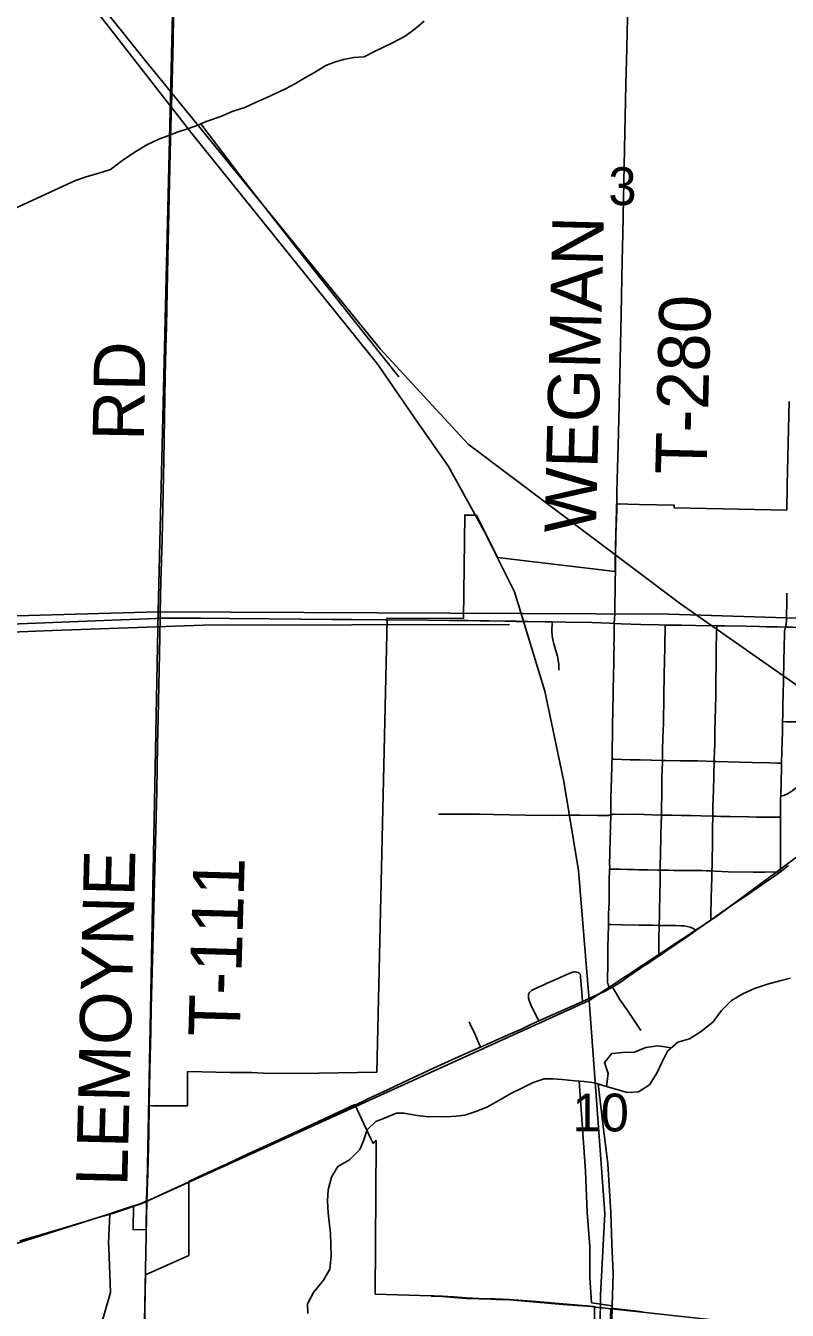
# Model space of a CAD drawing. Extents: x 0 to 34, y 0 to 22.
# Drawn here: x 3.939 to 4.781, y 16.776 to 18.197 of the extents above; entities that cross this region are included whole.
import ezdxf

# ---------------------------------------------------------------- set-up
doc = ezdxf.new("R2010")
doc.units = 0
for name, color, linetype in [('GM_X_City_Street', 7, 'Continuous'), ('GM_X_Corporation', 7, 'Continuous'), ('GM_X_Major_River', 7, 'Continuous'), ('GM_X_Minor_River', 7, 'Continuous'), ('GM_X_Rail_Line', 7, 'Continuous'), ('GM_X_Section', 7, 'Continuous'), ('GM_X_Section_Text', 7, 'Continuous'), ('GM_X_State_Route', 7, 'Continuous'), ('GM_X_Township_Road', 7, 'Continuous'), ('GM_X_Township_Road_Text', 7, 'Continuous')]:
    doc.layers.add(name, color=color, linetype=linetype)

msp = doc.modelspace()

# ---------------------------------------------------------------- linework, layer by layer
at = {"layer": 'GM_X_City_Street'}
for points in [[(4.7737, 17.2612), (4.7739, 17.2852), (4.7737, 17.2912), (4.7737, 17.3021), (4.774, 17.3144), (4.7739, 17.3214), (4.7738, 17.3284), (4.774, 17.3426), (4.7741, 17.3448), (4.7744, 17.3612), (4.7748, 17.3752), (4.7749, 17.3813), (4.7753, 17.3954), (4.776, 17.4155), (4.7762, 17.4247), (4.7762, 17.4273), (4.7763, 17.434), (4.7765, 17.4479), (4.7767, 17.4557), (4.777, 17.4743), (4.7778, 17.5116), (4.7781, 17.5225), (4.7784, 17.5271), (4.7795, 17.5318), (4.7802, 17.5355), (4.7804, 17.5386), (4.781, 17.5651), (4.781, 17.5694)], [(4.5286, 17.4843), (4.5284, 17.4905), (4.5279, 17.4951), (4.5271, 17.4997), (4.5253, 17.5057), (4.523, 17.5132), (4.5219, 17.5179), (4.5211, 17.5226), (4.5208, 17.5275), (4.5209, 17.5297), (4.5213, 17.5347), (4.5214, 17.5376)], [(4.5849, 17.1319), (4.5842, 17.1337), (4.5832, 17.1361), (4.5824, 17.1393), (4.5824, 17.1432), (4.5824, 17.1479), (4.5826, 17.1525), (4.5827, 17.1582), (4.5828, 17.1675), (4.5827, 17.1738), (4.5829, 17.18), (4.5831, 17.1878), (4.5831, 17.1893), (4.5834, 17.2017), (4.5834, 17.2028), (4.5834, 17.208), (4.5836, 17.2141), (4.5841, 17.228), (4.5842, 17.2311), (4.5842, 17.2435), (4.5843, 17.2451), (4.5844, 17.2558), (4.5845, 17.2589), (4.5847, 17.2641), (4.5848, 17.2651), (4.5846, 17.2713), (4.5848, 17.2791), (4.5854, 17.3008), (4.5856, 17.3024), (4.5856, 17.3039), (4.5855, 17.3055), (4.5856, 17.3071), (4.5856, 17.3101), (4.5859, 17.3243), (4.586, 17.3318), (4.5862, 17.3412), (4.5862, 17.3443), (4.5863, 17.352), (4.5868, 17.3657), (4.5871, 17.3768), (4.5873, 17.3824), (4.5874, 17.3857), (4.5876, 17.3981), (4.5878, 17.412), (4.5878, 17.4153), (4.5879, 17.4206), (4.588, 17.4285), (4.5882, 17.4345), (4.5883, 17.4445), (4.5885, 17.4525), (4.5886, 17.4556), (4.5886, 17.4586), (4.5887, 17.4632), (4.589, 17.4772), (4.5893, 17.4942), (4.5894, 17.4989), (4.5895, 17.5018), (4.5896, 17.5095), (4.5895, 17.5126), (4.5897, 17.5175), (4.5899, 17.5358)], [(4.5899, 17.5358), (4.5976, 17.5353), (4.6193, 17.5349), (4.6394, 17.5342), (4.6462, 17.5341), (4.6642, 17.5339), (4.6796, 17.5337), (4.7033, 17.5332), (4.7121, 17.5331), (4.7353, 17.5327), (4.7507, 17.5324), (4.7584, 17.5323), (4.7708, 17.532), (4.7795, 17.5318)], [(4.6391, 17.1677), (4.6392, 17.1767), (4.6393, 17.1869), (4.6395, 17.2017), (4.6398, 17.2135), (4.64, 17.2197), (4.6403, 17.2336), (4.6404, 17.2413), (4.6405, 17.2459), (4.6405, 17.2519), (4.6405, 17.255), (4.6406, 17.2628), (4.6411, 17.2859), (4.6414, 17.2951), (4.6415, 17.3028), (4.6417, 17.3136), (4.642, 17.3239), (4.642, 17.326), (4.6424, 17.3525), (4.6427, 17.3664), (4.6431, 17.382), (4.6431, 17.3842), (4.6434, 17.3961), (4.6437, 17.4094), (4.6441, 17.4176), (4.6443, 17.4254), (4.6447, 17.4549), (4.645, 17.4798), (4.6457, 17.5092), (4.646, 17.5201), (4.6462, 17.5247), (4.6462, 17.5292), (4.6462, 17.5341)], [(4.6967, 17.2076), (4.6967, 17.2118), (4.6966, 17.2178), (4.697, 17.2271), (4.6971, 17.2334), (4.6973, 17.2421), (4.6977, 17.2563), (4.6979, 17.262), (4.6981, 17.2675), (4.6983, 17.273), (4.6983, 17.2807), (4.6984, 17.2855), (4.6985, 17.293), (4.6985, 17.3008), (4.6985, 17.3071), (4.6985, 17.3125), (4.6989, 17.3191), (4.6989, 17.3226), (4.6989, 17.3254), (4.6989, 17.33), (4.699, 17.333), (4.6994, 17.3423), (4.6997, 17.3515), (4.6997, 17.3577), (4.6999, 17.3608), (4.7, 17.367), (4.7001, 17.3733), (4.7003, 17.3779), (4.7003, 17.381), (4.7004, 17.3831), (4.7007, 17.3965), (4.701, 17.4012), (4.7011, 17.41), (4.7013, 17.4155), (4.7013, 17.4206), (4.7015, 17.4255), (4.7016, 17.4329), (4.7018, 17.4392), (4.7018, 17.4456), (4.7021, 17.4528), (4.7022, 17.4609), (4.7024, 17.4743), (4.7025, 17.4887), (4.7025, 17.4948), (4.7026, 17.4964), (4.7026, 17.4994), (4.7026, 17.5017), (4.7026, 17.5047), (4.7026, 17.5078), (4.7027, 17.5109), (4.7028, 17.5125), (4.7028, 17.514), (4.703, 17.5186), (4.7031, 17.5216), (4.7031, 17.527), (4.7032, 17.5308), (4.7033, 17.5332)], [(4.7795, 17.5318), (4.7872, 17.5316), (4.7966, 17.5314), (4.8059, 17.5312), (4.8168, 17.531), (4.8447, 17.5304), (4.8634, 17.53), (4.8883, 17.5295), (4.9073, 17.5294), (4.9288, 17.529), (4.94, 17.5288), (4.9598, 17.5286), (4.9721, 17.5284), (4.9769, 17.5283), (4.9955, 17.5277), (5.0036, 17.5276), (5.022, 17.5274), (5.0454, 17.5271), (5.0671, 17.5267), (5.0843, 17.5265), (5.0927, 17.5264)], [(4.8685, 17.3321), (4.8638, 17.3386), (4.8565, 17.3485), (4.8472, 17.3609), (4.8392, 17.3722), (4.8311, 17.3834), (4.8274, 17.3885), (4.8228, 17.3947), (4.8162, 17.4033), (4.8051, 17.4181), (4.8015, 17.4232), (4.8005, 17.4243), (4.7993, 17.4252), (4.798, 17.426), (4.7966, 17.4265), (4.7951, 17.4268), (4.792, 17.4271), (4.7905, 17.4271), (4.7874, 17.4271), (4.783, 17.4272), (4.7802, 17.4272), (4.7762, 17.4273)], [(4.5874, 17.3857), (4.5899, 17.3856), (4.5982, 17.3854), (4.6074, 17.3851), (4.6184, 17.385), (4.631, 17.3846), (4.6431, 17.3842), (4.6464, 17.3841), (4.663, 17.384), (4.6739, 17.3839), (4.6822, 17.3838), (4.7004, 17.3831), (4.7034, 17.3831), (4.7161, 17.3828), (4.7283, 17.3824), (4.7423, 17.3821), (4.7618, 17.3817), (4.7702, 17.3813), (4.7749, 17.3813)], [(4.7741, 17.3448), (4.7777, 17.3456), (4.7815, 17.3472), (4.7863, 17.3504), (4.787, 17.3509), (4.795, 17.357), (4.8036, 17.3636), (4.8123, 17.3697), (4.8174, 17.3737), (4.8212, 17.3764), (4.829, 17.3818), (4.8311, 17.3834)], [(4.3952, 17.3249), (4.4039, 17.3249), (4.4174, 17.3249), (4.4406, 17.3247), (4.4561, 17.3243), (4.492, 17.3238), (4.5213, 17.3235), (4.5414, 17.3237), (4.5522, 17.3237), (4.5708, 17.3233), (4.5806, 17.3233), (4.5822, 17.3234), (4.5834, 17.3235), (4.5859, 17.3243), (4.5877, 17.3246), (4.5885, 17.3247), (4.5893, 17.3247), (4.5989, 17.3246), (4.6144, 17.3247), (4.6315, 17.3241), (4.642, 17.3239), (4.6439, 17.3239), (4.6532, 17.3237), (4.664, 17.3235), (4.6671, 17.3235), (4.6748, 17.3233), (4.6856, 17.323), (4.6989, 17.3226), (4.7026, 17.3225), (4.7077, 17.3224), (4.7183, 17.3222), (4.7385, 17.3218), (4.7477, 17.3217), (4.7522, 17.3217), (4.7615, 17.3214), (4.771, 17.3214), (4.7739, 17.3214)], [(4.5847, 17.2641), (4.5878, 17.264), (4.5965, 17.2639), (4.6044, 17.2638), (4.6119, 17.2637), (4.6162, 17.2634), (4.6208, 17.2633), (4.6269, 17.2632), (4.6376, 17.263), (4.6406, 17.2628), (4.6422, 17.2628), (4.6468, 17.2627), (4.6499, 17.2627), (4.6561, 17.2626), (4.673, 17.2625), (4.6868, 17.2625), (4.6914, 17.2623), (4.6979, 17.262), (4.7017, 17.2617), (4.716, 17.2611), (4.7438, 17.2608), (4.7485, 17.2607), (4.7514, 17.2607), (4.7564, 17.2608), (4.7737, 17.2612)], [(4.5834, 17.2028), (4.5861, 17.2027), (4.599, 17.2025), (4.6174, 17.2022), (4.6329, 17.2019), (4.6395, 17.2017), (4.6485, 17.2015), (4.6578, 17.2015), (4.664, 17.2013), (4.6671, 17.2011), (4.6705, 17.2006), (4.674, 17.1999), (4.6772, 17.1985), (4.6803, 17.1962)], [(4.5064, 17.096), (4.5003, 17.1084), (4.4976, 17.1139), (4.4958, 17.1185), (4.4951, 17.1213), (4.4949, 17.1239), (4.4951, 17.1257), (4.4956, 17.127), (4.4967, 17.1284), (4.4983, 17.1297), (4.5013, 17.1313), (4.5054, 17.1332), (4.5126, 17.1364), (4.5157, 17.1378), (4.5228, 17.1408), (4.538, 17.1477), (4.5438, 17.15), (4.5452, 17.1503), (4.5467, 17.1502), (4.5482, 17.15), (4.5498, 17.1496), (4.5511, 17.1488), (4.552, 17.1477), (4.5525, 17.1462), (4.5527, 17.1446), (4.554, 17.1277), (4.5548, 17.1177)], [(4.6194, 17.0855), (4.6038, 17.1086), (4.5957, 17.1203), (4.5918, 17.1269), (4.5901, 17.1297), (4.5879, 17.1334)], [(4.442, 17.067), (4.4398, 17.0721), (4.4379, 17.0765), (4.4366, 17.0793), (4.4347, 17.0835), (4.432, 17.0891), (4.4294, 17.0949)]]:
    msp.add_lwpolyline(points, dxfattribs=at)
at = {"layer": 'GM_X_Corporation'}
for points in [[(4.0222, 16.7599), (4.0326, 16.7955), (4.0305, 16.8455), (4.0303, 16.8501), (4.0317, 16.8827), (4.0367, 16.8844), (4.0522, 16.8896), (4.0578, 16.8916), (4.0574, 16.8651), (4.0718, 16.8647), (4.0724, 16.8974), (4.0735, 16.9278), (4.0747, 16.9726), (4.0749, 17.0026), (4.0791, 17.0021), (4.1175, 17.0022), (4.1178, 17.0401), (4.1649, 17.0389), (4.1886, 17.0388), (4.2084, 17.0378), (4.2629, 17.0381), (4.3271, 17.0392), (4.3385, 17.5406), (4.3385, 17.5419), (4.4229, 17.5412), (4.4245, 17.6558), (4.4374, 17.6557), (4.4606, 17.6087), (4.5909, 17.5932), (4.591, 17.6078), (4.5915, 17.6344), (4.5924, 17.6621), (4.5924, 17.6681), (4.6175, 17.6674), (4.6562, 17.6667), (4.6561, 17.664), (4.7808, 17.6613), (4.7813, 17.6888), (4.7833, 17.7815)], [(4.5674, 16.6831), (4.5681, 16.78), (4.5593, 16.7809), (4.5329, 16.783), (4.5035, 16.7856), (4.4741, 16.7879), (4.4586, 16.7885), (4.4399, 16.789), (4.426, 16.7896), (4.412, 16.7906), (4.3997, 16.7916), (4.3903, 16.7918), (4.3872, 16.7918), (4.3253, 16.7936), (4.3263, 16.9616), (4.3263, 16.9637), (4.3257, 16.9634), (4.3255, 16.9631), (4.3248, 16.9625), (4.3239, 16.9612), (4.3235, 16.9609), (4.3232, 16.9605), (4.3208, 16.9649), (4.3028, 17.0035), (4.2909, 16.9979), (4.246, 16.9771), (4.2052, 16.9582), (4.1854, 16.9493), (4.1615, 16.9381), (4.1362, 16.9264), (4.1191, 16.9185), (4.1191, 16.8363), (4.071, 16.8152), (4.0678, 16.6389)], [(4.6211, 16.7743), (4.5862, 16.7781), (4.5828, 16.6728)]]:
    msp.add_lwpolyline(points, dxfattribs=at)
at = {"layer": 'GM_X_Major_River'}
msp.add_lwpolyline([(4.7849, 17.1432), (4.7731, 17.1404), (4.7594, 17.1366), (4.7449, 17.132), (4.7323, 17.1259), (4.7196, 17.1186), (4.7087, 17.1075), (4.6993, 17.0952), (4.6862, 17.0845), (4.6731, 17.0764), (4.6601, 17.0726), (4.6489, 17.0626), (4.6425, 17.0499), (4.6369, 17.0382), (4.6287, 17.0255), (4.6167, 17.0175), (4.6046, 17.017), (4.5926, 17.0203), (4.5813, 17.0236), (4.5681, 17.0274), (4.5564, 17.0292), (4.5462, 17.0298), (4.5322, 17.0313), (4.522, 17.0319), (4.5122, 17.0318), (4.5003, 17.0279), (4.4877, 17.0217), (4.4754, 17.0156), (4.462, 17.0079), (4.4489, 17.0007), (4.4367, 16.996), (4.4245, 16.9918), (4.415, 16.9905), (4.4044, 16.99), (4.3945, 16.9902), (4.3847, 16.9901), (4.3718, 16.9915), (4.357, 16.994), (4.3488, 16.994), (4.3358, 16.9886), (4.3262, 16.9846), (4.3165, 16.9754), (4.3124, 16.9633), (4.3084, 16.9536), (4.2968, 16.9425), (4.2841, 16.9348), (4.277, 16.9232), (4.2732, 16.9093), (4.2725, 16.8968), (4.2733, 16.8838), (4.2749, 16.8705), (4.2758, 16.861), (4.2762, 16.8481), (4.2767, 16.8356), (4.2752, 16.8215), (4.2681, 16.8092), (4.2571, 16.7954), (4.2504, 16.7831), (4.2509, 16.7724)], dxfattribs=at)
at = {"layer": 'GM_X_Minor_River'}
for points in [[(4.3795, 18.2024), (4.3698, 18.1942), (4.3586, 18.1858), (4.3444, 18.1782), (4.3245, 18.1688), (4.313, 18.163), (4.3016, 18.1621), (4.2902, 18.1601), (4.2803, 18.1569), (4.2707, 18.1534), (4.258, 18.1457), (4.2481, 18.1399), (4.2373, 18.1333), (4.2262, 18.1275), (4.2047, 18.1174), (4.1928, 18.1124), (4.181, 18.107), (4.1672, 18.1024), (4.1546, 18.097), (4.1382, 18.0913), (4.1271, 18.0866), (4.1175, 18.0831), (4.1072, 18.0799), (4.0957, 18.0756), (4.0858, 18.0717), (4.0728, 18.0656), (4.0585, 18.0572), (4.0447, 18.0473), (4.0323, 18.0381), (4.0194, 18.0342), (4.0056, 18.03), (3.9938, 18.0261), (3.6854, 17.8841)], [(4.1324, 18.0889), (4.1764, 18.0308), (4.2421, 17.9469), (4.3123, 17.8579), (4.3516, 17.8087)], [(3.1069, 17.509), (3.2588, 17.5092), (3.4686, 17.5105), (3.6937, 17.5172), (3.9682, 17.5281), (4.1353, 17.5339), (4.2993, 17.5345), (4.4739, 17.5348)], [(4.6532, 17.0664), (4.6381, 17.0686), (4.6248, 17.0666), (4.6121, 17.0616), (4.5989, 17.0612), (4.5871, 17.0599), (4.5789, 17.0499), (4.5831, 17.038), (4.5813, 17.0236)], [(4.5512, 17.0295), (4.555, 16.9719), (4.5581, 16.9297), (4.56, 16.8841), (4.5629, 16.8465), (4.5628, 16.8123), (4.5647, 16.7842), (4.5874, 16.7809)], [(4.5719, 17.0263), (4.5772, 16.9824), (4.5826, 16.9378), (4.5861, 16.8839), (4.5872, 16.8493), (4.5885, 16.8165), (4.5874, 16.7809), (4.587, 16.7468), (4.5863, 16.7126), (4.5853, 16.6664), (4.5854, 16.6087), (4.5805, 16.5511), (4.5796, 16.4973), (4.5762, 16.4351), (4.574, 16.3627), (4.5739, 16.2667), (4.5716, 16.2193), (4.5666, 16.1575), (4.5623, 16.089)]]:
    msp.add_lwpolyline(points, dxfattribs=at)
at = {"layer": 'GM_X_Rail_Line'}
for points in [[(3.4414, 20.9), (3.5016, 20.5918), (3.7507, 19.321), (3.8733, 18.7042), (3.9207, 18.4339), (3.9385, 18.3568), (3.9629, 18.2975), (3.9974, 18.239), (4.1223, 18.078), (4.3281, 17.8226), (4.3689, 17.7633), (4.4066, 17.7097), (4.4454, 17.6387), (4.4793, 17.5709), (4.5132, 17.4611), (4.5342, 17.361), (4.5504, 17.2625), (4.562, 17.1188)], [(3.6732, 20.9), (3.6471, 20.09), (3.6471, 19.9081), (3.752, 19.3659), (3.9326, 18.4227), (3.949, 18.3555), (3.9754, 18.3001), (4.0116, 18.2329), (4.0712, 18.1586), (4.3307, 17.8397), (4.4282, 17.7343), (4.663, 17.5576), (4.8455, 17.4299), (4.9093, 17.3662)], [(4.562, 17.1188), (4.7045, 17.2127), (4.8656, 17.3321), (4.9093, 17.3662)], [(2.1, 16.989), (2.137, 17.008), (2.2064, 17.0481), (2.2635, 17.0798), (2.2874, 17.0883), (2.3198, 17.0929), (2.3422, 17.089), (2.7364, 16.991), (2.7673, 16.9841), (2.7943, 16.9864), (2.8612, 16.9919), (2.9494, 16.9811), (3.3041, 16.8562), (3.4786, 16.8144), (3.5457, 16.804), (3.7963, 16.8323), (3.9156, 16.8457), (4.0662, 16.8935), (4.562, 17.1188)], [(4.562, 17.1188), (4.5796, 16.883), (4.5748, 16.7925), (4.5733, 16.6553), (4.5685, 16.4905), (4.5573, 16.0706), (4.559, 15.9996), (4.5639, 15.9172), (4.5639, 15.8252), (4.5607, 15.7154), (4.5448, 15.1679), (4.5209, 14.2861), (4.5155, 14.1)]]:
    msp.add_lwpolyline(points, dxfattribs=at)
at = {"layer": 'GM_X_Section'}
for points in [[(3.1307, 18.5181), (4.1085, 18.519), (4.0852, 17.5486), (3.0931, 17.5206), (3.1239, 18.5181)], [(4.1339, 18.5191), (5.1123, 18.5161), (5.0874, 17.5326), (4.6502, 17.5462), (4.0852, 17.5486), (4.1085, 18.519)], [(4.0852, 17.5486), (4.0656, 16.5335), (3.0627, 16.5204), (3.0931, 17.5206)], [(5.0874, 17.5326), (5.0695, 16.5364), (4.0656, 16.5335), (4.0852, 17.5486), (4.6502, 17.5462)]]:
    msp.add_lwpolyline(points, close=True, dxfattribs=at)
at = {"layer": 'GM_X_State_Route'}
msp.add_line((4.303, 17.003), (4.3145, 17.0085), dxfattribs=at)
for points in [[(4.571, 17.1251), (4.5789, 17.1287), (4.5849, 17.1319), (4.5879, 17.1334), (4.5897, 17.1344), (4.5986, 17.1402), (4.6049, 17.1447), (4.6151, 17.1517), (4.6227, 17.1569), (4.6265, 17.1594), (4.6367, 17.1661), (4.6391, 17.1677), (4.643, 17.1704), (4.6481, 17.1738), (4.6595, 17.1817), (4.6709, 17.1896), (4.6803, 17.1962), (4.6899, 17.2029), (4.6967, 17.2076), (4.7039, 17.2127), (4.7179, 17.2225), (4.7372, 17.2356), (4.7474, 17.2425), (4.7639, 17.2541), (4.7737, 17.2612), (4.7828, 17.2681)], [(4.3781, 17.0382), (4.3907, 17.0441), (4.402, 17.0492), (4.4217, 17.0582), (4.4401, 17.0662), (4.442, 17.067), (4.4518, 17.0713), (4.4723, 17.0805), (4.4878, 17.0874), (4.4961, 17.0914), (4.5032, 17.0945), (4.5064, 17.096), (4.5148, 17.0999), (4.5198, 17.102), (4.5283, 17.1056), (4.5368, 17.1094), (4.5507, 17.1158), (4.5548, 17.1177), (4.5691, 17.1241), (4.571, 17.1251)], [(4.3145, 17.0085), (4.3163, 17.0094), (4.3389, 17.0198), (4.363, 17.0312), (4.3772, 17.0378), (4.3781, 17.0382)], [(4.1193, 16.918), (4.1364, 16.9259), (4.1618, 16.9376), (4.1856, 16.9488), (4.2054, 16.9576), (4.2462, 16.9766), (4.2912, 16.9974), (4.303, 17.003)], [(4.0727, 16.8968), (4.0752, 16.8978), (4.0999, 16.909), (4.1147, 16.9157), (4.1193, 16.918)], [(4.031, 16.8819), (4.0319, 16.8822), (4.037, 16.8838), (4.0525, 16.889), (4.058, 16.891)], [(4.058, 16.891), (4.0669, 16.8945), (4.0727, 16.8968)], [(3.932, 16.8528), (3.944, 16.8559), (3.9754, 16.8651), (4.0021, 16.8732), (4.0215, 16.8791), (4.031, 16.8819)]]:
    msp.add_lwpolyline(points, dxfattribs=at)
at = {"layer": 'GM_X_Township_Road'}
for points in [[(4.0873, 17.5417), (4.0874, 17.5475), (4.0882, 17.5823), (4.0895, 17.6283), (4.0906, 17.6818), (4.0913, 17.7159), (4.0923, 17.7632), (4.0929, 17.8092), (4.0936, 17.8397), (4.0943, 17.8651), (4.0955, 17.9223), (4.0963, 17.9577), (4.0984, 18.0566), (4.0991, 18.0858), (4.1003, 18.1212), (4.1016, 18.1809), (4.1026, 18.2331), (4.1036, 18.299), (4.1053, 18.3804), (4.1059, 18.4096), (4.1071, 18.4618), (4.1076, 18.4966), (4.1077, 18.5069)], [(4.5927, 17.6676), (4.5929, 17.6811), (4.5934, 17.7076), (4.5942, 17.7324), (4.5956, 17.793), (4.5967, 17.8443), (4.5975, 17.8785), (4.5988, 17.9376), (4.5995, 17.9671), (4.6001, 18.006), (4.6017, 18.0791), (4.6028, 18.1319), (4.6037, 18.1723), (4.6046, 18.2065), (4.6063, 18.2749), (4.6068, 18.3013), (4.6073, 18.32), (4.6082, 18.3448), (4.6095, 18.4086), (4.6103, 18.4412), (4.6118, 18.4878), (4.6121, 18.4972), (4.6125, 18.5055)], [(4.5911, 17.5926), (4.5912, 17.6072), (4.5917, 17.6338), (4.5926, 17.6615), (4.5927, 17.6676)], [(4.5899, 17.5358), (4.5903, 17.5408), (4.5904, 17.5471), (4.5905, 17.5567), (4.5907, 17.5737), (4.5909, 17.5848), (4.5911, 17.5926)], [(3.0949, 17.5166), (3.1165, 17.517), (3.174, 17.5179), (3.2212, 17.5188), (3.2596, 17.5196), (3.3016, 17.5204), (3.3861, 17.5216), (3.4366, 17.5223), (3.4676, 17.5228), (3.5154, 17.5236), (3.568, 17.5248), (3.5909, 17.5256), (3.6487, 17.5272), (3.6972, 17.5289), (3.7441, 17.53), (3.809, 17.5318), (3.8532, 17.5331), (3.9011, 17.5348), (3.9315, 17.5356), (4.0344, 17.5397), (4.0831, 17.5415), (4.0873, 17.5417)], [(4.0751, 17.0021), (4.0754, 17.0211), (4.0758, 17.0422), (4.0769, 17.0845), (4.0776, 17.11), (4.0782, 17.1373), (4.0792, 17.1765), (4.08, 17.205), (4.0805, 17.2212), (4.0836, 17.3505), (4.0846, 17.4014), (4.0851, 17.4313), (4.0867, 17.5021), (4.0873, 17.5417)], [(4.0873, 17.5417), (4.1061, 17.5418), (4.1325, 17.5416), (4.1637, 17.5414), (4.2088, 17.5409), (4.2774, 17.5404), (4.2992, 17.5402), (4.3363, 17.54), (4.3387, 17.54)], [(4.3387, 17.54), (4.3842, 17.5394), (4.4074, 17.5392), (4.4223, 17.539), (4.4283, 17.539), (4.4411, 17.5388)], [(4.4411, 17.5388), (4.451, 17.5387), (4.4697, 17.5384), (4.4808, 17.5383), (4.4818, 17.5382)], [(4.4818, 17.5382), (4.4887, 17.5382), (4.4942, 17.5381)], [(4.4942, 17.5381), (4.5134, 17.5377), (4.5214, 17.5376)], [(4.5214, 17.5376), (4.5368, 17.5373), (4.5649, 17.5369), (4.5851, 17.5361), (4.5899, 17.5358)], [(4.0727, 16.8968), (4.0738, 16.9273), (4.0749, 16.972), (4.0751, 17.0021)], [(4.3875, 16.7912), (4.3906, 16.7913), (4.3999, 16.791), (4.4123, 16.7901), (4.4262, 16.789), (4.4402, 16.7884), (4.4536, 16.7881)], [(4.4536, 16.7881), (4.4588, 16.7879), (4.4743, 16.7873), (4.5037, 16.785), (4.5331, 16.7824), (4.5595, 16.7804), (4.5683, 16.7795), (4.5692, 16.7794)], [(4.5692, 16.7794), (4.5765, 16.7786), (4.5864, 16.7776)], [(4.5864, 16.7776), (4.6213, 16.7738), (4.6815, 16.7673), (4.734, 16.7615), (4.7881, 16.7554), (4.7927, 16.755), (4.7958, 16.755), (4.7989, 16.7553), (4.803, 16.7559), (4.8061, 16.757), (4.8088, 16.7585)]]:
    msp.add_lwpolyline(points, dxfattribs=at)

# ---------------------------------------------------------------- texts
at = {"layer": 'GM_X_Section_Text'}
for s, height, p in [('3', 0.0419, (4.5834, 17.9988)), ('10', 0.04186, (4.5438, 16.9738))]:
    msp.add_text(s, height=height, rotation=0, dxfattribs=at).set_placement(p)
at = {"layer": 'GM_X_Township_Road_Text'}
for s, rotation, p in [('WEGMAN', 88.5149, (4.5694, 17.6355)), ('T-280', 88.5959, (4.692, 17.7002)), ('RD', 89.0116, (4.0694, 17.7377)), ('LEMOYNE', 88.6029, (4.051, 16.9127)), ('T-111', 88.3311, (4.1753, 17.0779))]:
    msp.add_text(s, height=0.05682, rotation=rotation, dxfattribs=at).set_placement(p)

doc.saveas('drawing.dxf')
